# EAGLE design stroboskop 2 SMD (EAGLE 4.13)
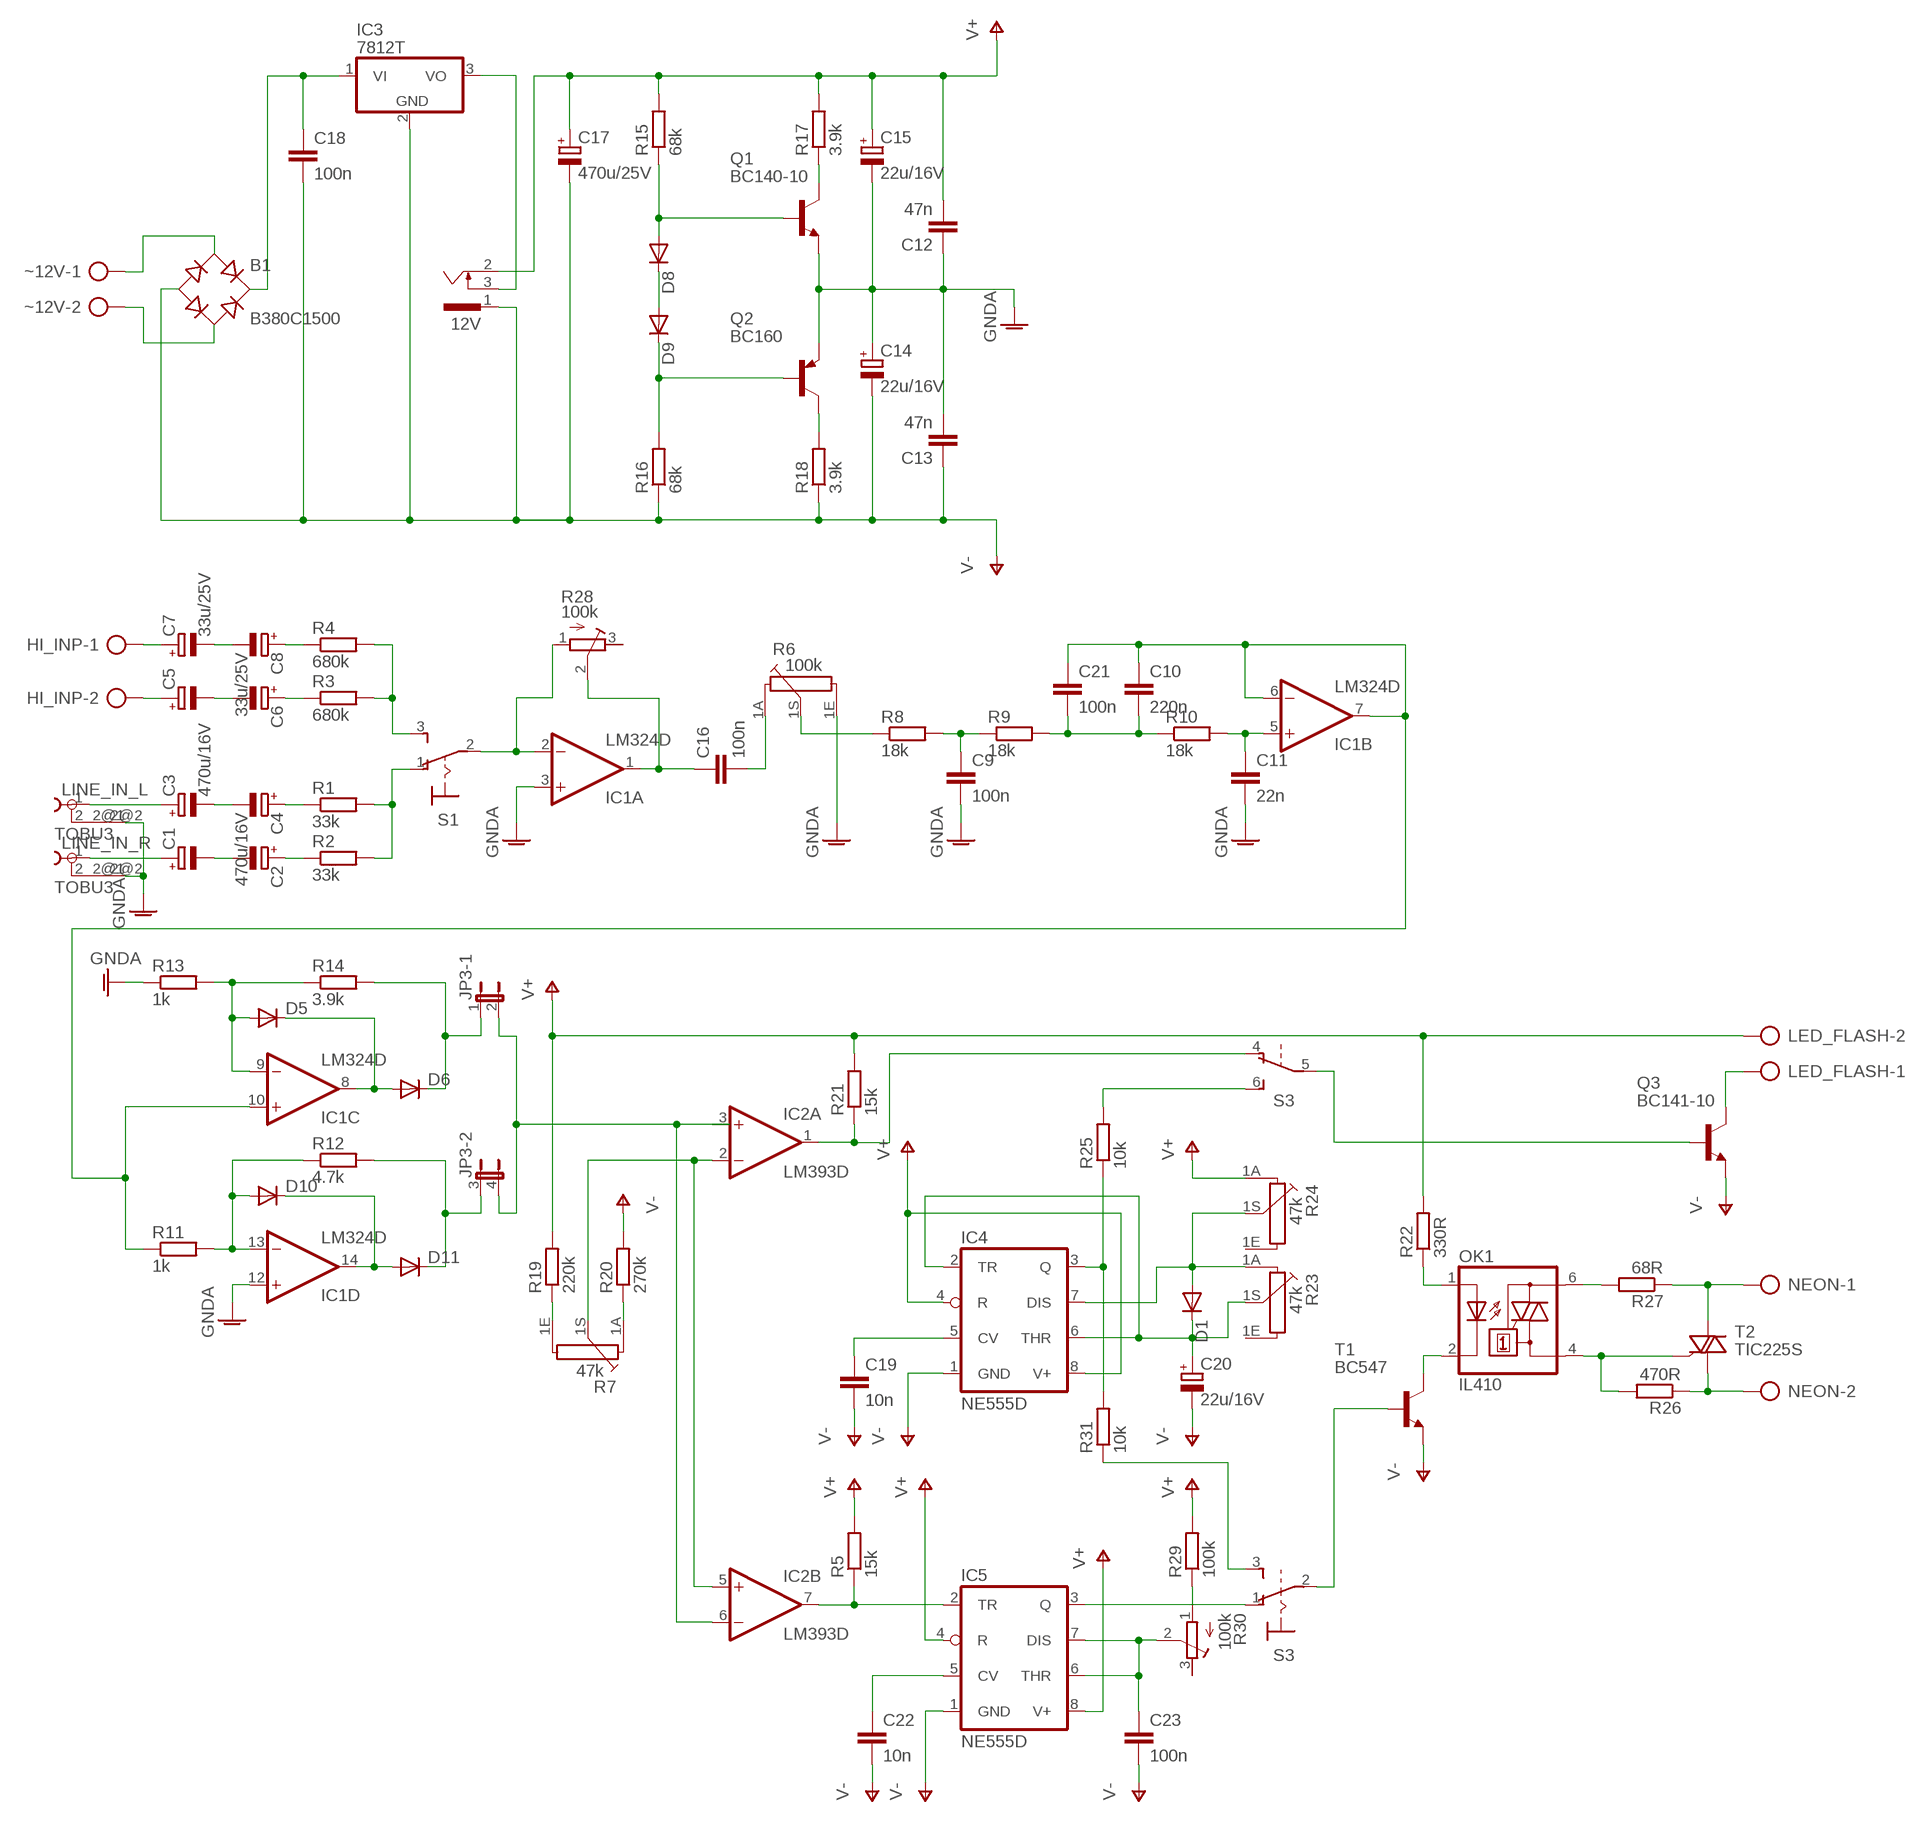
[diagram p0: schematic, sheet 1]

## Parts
12V  733989-55  [733989-5]
B1  B380C1500  RB1A  [RB1A]
C1  CPOL-EUE5-10.5  [E5-10,5]
C2  CPOL-EUE5-10.5  [E5-10,5]
C3  470u/16V  CPOL-EUE5-10.5  [E5-10,5]
C4  470u/16V  CPOL-EUE5-10.5  [E5-10,5]
C5  CPOL-EUE2.5-5  [E2,5-5]
C6  CPOL-EUE2.5-5  [E2,5-5]
C7  33u/25V  CPOL-EUE2.5-5  [E2,5-5]
C8  33u/25V  CPOL-EUE2.5-5  [E2,5-5]
C9  100n  C-EUC1206  [C1206]
C10  220n  C-EUC1206  [C1206]
C11  22n  C-EUC0805  [C0805]
C12  47n  C-EU050-025X075  [C050-025X075]
C13  47n  C-EU050-025X075  [C050-025X075]
C14  22u/16V  CPOL-EUE5-10.5  [E5-10,5]
C15  22u/16V  CPOL-EUE5-10.5  [E5-10,5]
C16  100n  C-EUC1206  [C1206]
C17  470u/25V  CPOL-EUE5-10.5  [E5-10,5]
C18  100n  C-EU050-025X075  [C050-025X075]
C19  10n  C-EUC0805  [C0805]
C20  22u/16V  CPOL-EUE2,5-6E  [E2,5-6E]
C21  100n  C-EUC1206  [C1206]
C22  10n  C-EUC0805  [C0805]
C23  100n  C-EUC1206  [C1206]
D1  DIODE-SOD80C  [SOD80C]
D5  DIODE-SOD80C  [SOD80C]
D6  DIODE-SOD80C  [SOD80C]
D8  DIODE-SOD80C  [SOD80C]
D9  DIODE-SOD80C  [SOD80C]
D10  DIODE-SOD80C  [SOD80C]
D11  DIODE-SOD80C  [SOD80C]
HI_INP  AK300/2  [AK300/2]
IC1  LM324D  [SO14]
IC2  LM393D  [SO08]
IC3  7812T  [TO220H]
IC4  NE555D  [SO08]
IC5  NE555D  [SO08]
JP3  JP2QE  [JP2Q]
LED_FLASH  AK300/2  [AK300/2]
LINE_IN_L  TOBU3  [TOBU3]
LINE_IN_R  TOBU3  [TOBU3]
NEON  AK300/2  [AK300/2]
OK1  IL410  [DIL06]
Q1  BC140-10  [TO39]
Q2  BC160  [TO39]
Q3  BC141-10  [TO39]
R1  33k  R-EU_M1206  [M1206]
R2  33k  R-EU_M1206  [M1206]
R3  680k  R-EU_M1206  [M1206]
R4  680k  R-EU_M1206  [M1206]
R5  15k  R-EU_M1206  [M1206]
R6  100k  PC16S  [PC16S]
R7  47k  PC16S  [PC16S]
R8  18k  R-EU_M1206  [M1206]
R9  18k  R-EU_M1206  [M1206]
R10  18k  R-EU_M1406  [M1406]
R11  1k  R-EU_M1206  [M1206]
R12  4.7k  R-EU_M1206  [M1206]
R13  1k  R-EU_M1206  [M1206]
R14  3.9k  R-EU_M1206  [M1206]
R15  68k  R-EU_M1206  [M1206]
R16  68k  R-EU_M1206  [M1206]
R17  3.9k  R-EU_M1206  [M1206]
R18  3.9k  R-EU_M1206  [M1206]
R19  220k  R-EU_M1206  [M1206]
R20  270k  R-EU_M1206  [M1206]
R21  15k  R-EU_M1206  [M1206]
R22  330R  R-EU_M1206  [M1206]
R23  47k  PC16S  [PC16S]
R24  47k  PC16S  [PC16S]
R25  10k  R-EU_M1206  [M1206]
R26  470R  R-EU_0309/12  [0309/12]
R27  68R  R-EU_0309/12  [0309/12]
R28  100k  R-TRIMM4G/J  [RTRIM4G/J]
R29  100k  R-EU_M1206  [M1206]
R30  100k  R-TRIMM4G/J  [RTRIM4G/J]
R31  10k  R-EU_M1206  [M1206]
S1  320-916  [320-916]
S3  320-938  [320-938]
T1  BC547  [TO92]
T2  TIC225S  [TO220DS]
~12V  AK300/2  [AK300/2]

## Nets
GNDA: C9.2 C11.2 C12.1 C13.2 C14.+ C15.- IC1.3(A:+IN) IC1.12(D:+IN) LINE_IN_L.2@2 LINE_IN_R.2@2 Q1.1(E) Q2.1(E) R6.1E R13.1
N$1: C7.- C8.-
N$2: C5.- C6.-
N$3: C3.- C4.-
N$4: C1.- C2.-
N$5: C4.+ R1.1
N$6: C2.+ R2.1
N$7: C8.+ R4.1
N$8: C6.+ R3.1
N$9: R3.2 R4.2 S1.3(S)
N$10: R1.2 R2.2 S1.1(O)
N$11: IC1.2(A:-IN) R28.1(E) S1.2(P)
N$12: C16.1 IC1.1(A:OUT) R28.2(S)
N$13: R6.1S R8.1
N$14: C9.1 R8.2 R9.1
N$15: C10.2 C21.2 R9.2 R10.1
N$16: C11.1 IC1.5(B:+IN) R10.2
N$17: C10.1 C21.1 IC1.6(B:-IN) IC1.7(B:OUT) IC1.10(C:+IN) R11.1
N$18: D10.A IC1.13(D:-IN) R11.2 R12.1
N$19: D10.C D11.A IC1.14(D:OUT)
N$20: D11.C JP3.3 R12.2
N$21: C16.2 R6.1A
N$22: D5.A IC1.9(C:-IN) R13.2 R14.1
N$23: D5.C D6.A IC1.8(C:OUT)
N$24: D6.C JP3.1 R14.2
N$25: IC2.3(A:+IN) IC2.6(B:-IN) JP3.2 JP3.4
N$26: IC2.2(A:-IN) IC2.5(B:+IN) R7.1S
N$27: C7.+ HI_INP.1
N$28: C5.+ HI_INP.2
N$29: C3.+ LINE_IN_L.1
N$30: C1.+ LINE_IN_R.1
N$31: IC2.1(A:OUT) R21.1 S3.4(B:O)
N$32: R7.1E R19.1
N$33: Q1.3(C) R17.1
N$34: Q2.3(C) R18.2
N$35: D8.A Q1.2(B) R15.1
N$36: D8.C D9.A
N$37: D9.C Q2.2(B) R16.2
N$38: R7.1A R20.1
N$39: LED_FLASH.1 Q3.3(C)
N$40: OK1.1(A) R22.1
N$41: OK1.2(C) T1.3(C)
N$42: B1.AC1 ~12V.1
N$43: B1.AC2 ~12V.2
N$44: B1.+ C18.1 IC3.1(VI)
N$45: R25.2 S3.6(B:S)
N$46: 12V.3 IC3.3(VO)
N$47: C19.1 IC4.5(CV)
N$48: C20.+ D1.C IC4.2(TR) IC4.6(THR) R23.1S
N$49: OK1.4(A1) R26.2 T2.G
N$50: D1.A IC4.7(DIS) R23.1A R24.1S
N$51: NEON.2 R26.1 T2.A1
N$52: IC4.3(Q) R25.1 R31.2
N$53: Q3.2(B) S3.5(B:P)
N$54: OK1.6(A2) R27.2
N$55: NEON.1 R27.1 T2.A2
N$60: IC2.7(B:OUT) IC5.2(TR) R5.1
N$69: C22.1 IC5.5(CV)
N$70: R29.1 R30.1(E)
N$71: C23.1 IC5.6(THR) IC5.7(DIS) R30.2(S)
N$72: S3.2(1:P) T1.2(B)
N$73: IC5.3(Q) S3.1(1:O)
N$74: R31.1 S3.3(1:S)
V+: 12V.2 C12.2 C15.+ C17.+ IC4.4(R) IC4.8(V+) IC5.4(R) IC5.8(V+) LED_FLASH.2 R5.2 R15.2 R17.2 R19.2 R21.2 R22.2 R24.1A R29.2
V-: 12V.1 B1.- C13.1 C14.- C17.- C18.2 C19.2 C20.- C22.2 C23.2 IC3.2(GND) IC4.1(GND) IC5.1(GND) Q3.1(E) R16.1 R18.1 R20.2 T1.1(E)
Unconnected: LINE_IN_L.2 LINE_IN_L.2@1 LINE_IN_R.2 LINE_IN_R.2@1 R23.1E R24.1E R28.3(A) R30.3(A)

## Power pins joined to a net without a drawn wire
V+: IC1.4(P:V+) IC2.8(P:V+)
V-: IC1.11(P:V-) IC2.4(P:V-)

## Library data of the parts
12V = con-conrad:733989-55: FEMALE PRINT CONNECTOR Außen-Ø 4,2 mm, Innen 1.1 mm FUK HING Industries, distributor Conrad
B1 = rectifier:RB1A: RECTIFIER 1 A
C1-C8 C14 C15 C17 C20 = rcl:CPOL-EU: POLARIZED CAPACITOR, European symbol
C9-C13 C16 C18 C19 C21-C23 = rcl:C-EU: CAPACITOR, European symbol
D1 D5 D6 D8-D11 = diode:DIODE-: DIODE
HI_INP LED_FLASH NEON ~12V = con-ptr500:AK300/2: CONNECTOR
IC1 = linear:LM324: OP AMP
IC2 = linear:LM393: COMPARATOR
IC3 = linear:78*: Positive VOLTAGE REGULATOR
IC4 IC5 = linear:*555: TIMER
JP3 = jumper:JP2QE: JUMPER
LINE_IN_L LINE_IN_R = con-hirschmann:TOBU3: Female Cinch CONNECTOR
OK1 = optocoupler:IL410: SIEMENS OPTO COUPLER
Q1 = transistor-npn:BC140-10: NPN Transistor
Q2 = transistor-pnp:BC160*: PNP Transistror
Q3 = transistor-npn:BC141-10: NPN Transistor
R1-R5 R8-R22 R25-R27 R29 R31 = rcl:R-EU_: RESISTOR, European symbol
R6 R7 R23 R24 = piher:PC16S: POTENTIOMETER single carbon potentiometer, 16 mm, S3ROH
R28 R30 = rcl:R-TRIMM: Trimm resistor
S1 = switch:320-916: TOGGLE SWITCH distributor RS Components
S3 = switch:320-938: TOGGLE SWITCH distributor RS Components
T1 = transistor:BC547: NPN TRANSISTOR
T2 = triac:TIC225S: TRIAC

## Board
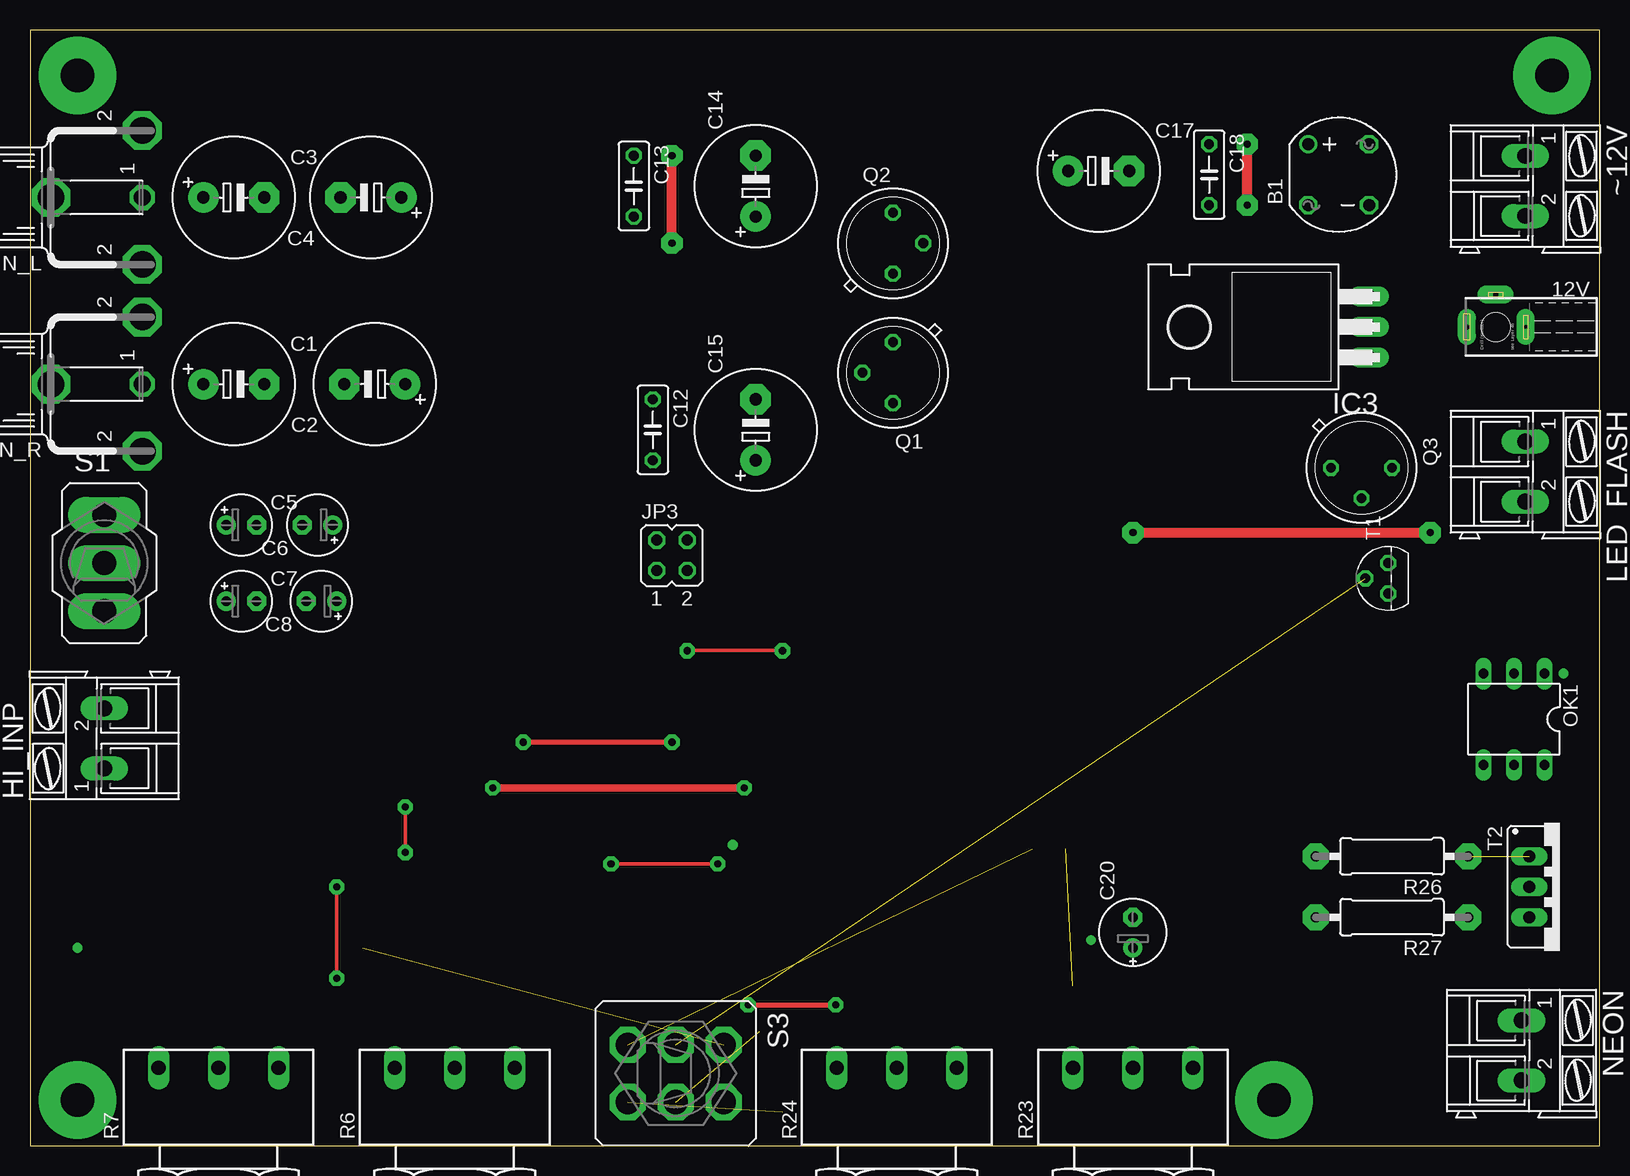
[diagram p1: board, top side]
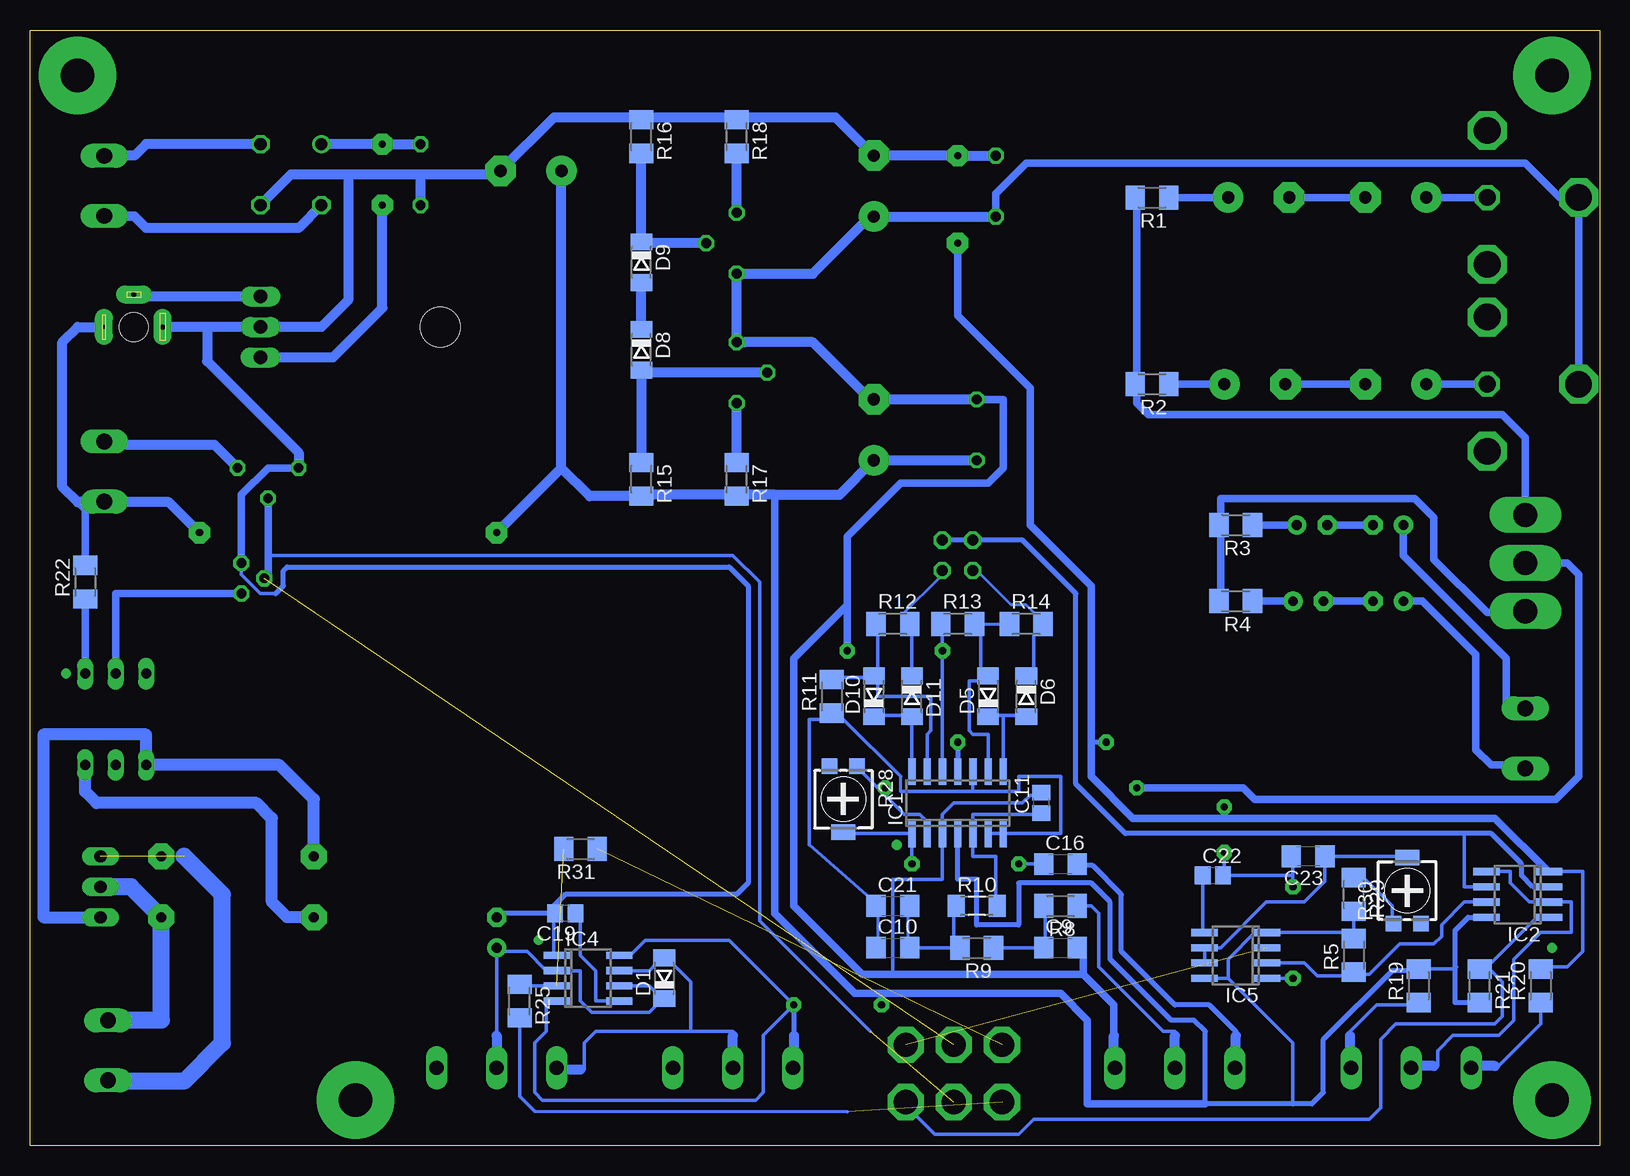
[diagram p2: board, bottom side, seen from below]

Size 130.8 x 93.02 mm. Coordinates in mm from the lower left corner, seen from the top.
Outline: 0,0 130.8,0 130.8,93.02 0,93.02 0,0
Copper layers (1*16): Top 0.035mm / dielectric 1.5mm / Bottom 0.035mm
Design rules "default": minimum track width 12mil, minimum drill 5mil, track to track 10mil, track to pad 10mil, pad to pad 10mil, via to via 10mil, smd to smd 10mil, copper to edge 40mil, drill to drill 8mil, minimum pad ring 10mil, minimum via ring 8mil, stop-mask expansion 4mil, vias tented up to drill 0mil, thermal gap 10mil

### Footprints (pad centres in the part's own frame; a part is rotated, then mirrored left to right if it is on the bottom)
733989-5 = drill 0.4 pad 1.5 long: 1 0,5.82; 3 2.7,3.42 | drill 0.3 pad 1.5 long: 2 0,0.92 | hole 2.4: 0,3.42
RB1A = drill 1.016 round: + -2.54,2.54 | drill 1.016 octagon: - 2.54,-2.54; AC1 2.54,2.54; AC2 -2.54,-2.54
E5-10,5 = drill 1.016 pad 2.54 round: + -2.54,0 | drill 1.016 pad 2.54 octagon: - 2.54,0
E2,5-5 = drill 0.813 pad 1.6 round: + -1.27,0 | drill 0.813 pad 1.6 octagon: - 1.27,0
C1206 = smd 1.6 x 1.8: 1 -1.4,0; 2 1.4,0
C0805 = smd 1.3 x 1.5: 1 -0.85,0; 2 0.85,0
C050-025X075 = drill 0.813 octagon: 1 -2.54,0; 2 2.54,0
E2,5-6E = drill 0.813 pad 1.575 round: + -1.27,0 | drill 0.813 pad 1.575 octagon: - 1.27,0
SOD80C = smd 1.4 x 1.8: A 1.7,0; C -1.7,0
AK300/2 = drill 1.321 long: 1 -2.515,0; 2 2.489,0
SO14 = smd 0.6 x 2.2: 1 -3.81,-2.6; 2 -2.54,-2.6; 3 -1.27,-2.6; 4 0,-2.6; 5 1.27,-2.6; 6 2.54,-2.6; 7 3.81,-2.6; 8 3.81,2.6; 9 2.54,2.6; 10 1.27,2.6; 11 0,2.6; 12 -1.27,2.6; 13 -2.54,2.6; 14 -3.81,2.6
SO08 = smd 0.6 x 2.2: 1 -1.905,-2.6; 2 -0.635,-2.6; 3 0.635,-2.6; 4 1.905,-2.6; 5 1.905,2.6; 6 0.635,2.6; 7 -0.635,2.6; 8 -1.905,2.6
TO220H = drill 1.118 long: 1 -2.54,-10.16; 2 0,-10.16; 3 2.54,-10.16 | hole 3.302: 0,4.826
JP2Q = drill 0.914 octagon: 1 -1.27,-1.27; 2 -1.27,1.27; 3 1.27,-1.27; 4 1.27,1.27
TOBU3 = drill 1.397 octagon: 1 0,-2.54 | drill 2.21 octagon: 2 5.588,-2.54; 2@1 -5.588,-2.54; 2@2 0,5.08
DIL06 = drill 0.813 long: 1 -2.54,-3.81; 2 0,-3.81; 3 2.54,-3.81; 4 2.54,3.81; 5 0,3.81; 6 -2.54,3.81
TO39 = drill 0.813 octagon: 1 0,-2.54; 2 2.54,0; 3 0,2.54
M1206 = smd 1.6 x 2: 1 -1.4,0; 2 1.4,0
PC16S = drill 1.2 long: 1A -5,6.5; 1E 5,6.5; 1S 0,6.5
M1406 = smd 1.4 x 1.8: 1 -1.7,0; 2 1.7,0
0309/12 = drill 0.813 octagon: 1 -6.35,0; 2 6.35,0
RTRIM4G/J = smd 1.3 x 1.3: 1 -1.15,-2.75; 3 1.15,-2.75 | smd 2 x 1.3: 2 0,2.75
320-916 = drill 2.007 long: 1 0,4.013; 2 0,0; 3 0,-4.013
320-938 = drill 2.007 octagon: 1 -2.388,4.013; 2 -2.388,0; 3 -2.388,-4.013; 4 2.388,4.013; 5 2.388,0; 6 2.388,-4.013
TO92 = drill 0.813 octagon: 1 1.27,0; 2 0,1.905; 3 -1.27,0
TO220DS = drill 1.016 long: A1 -2.54,-2.54; A2 0,-2.54; G 2.54,-2.54

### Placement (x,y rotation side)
12V  125.56,68.26 90 top
B1  109.06,80.96 0 top
C1  16.98,63.49 0 top
C2  28.73,63.49 180 top
C3  16.98,79.05 0 top
C4  28.41,79.05 180 top
C5  17.61,51.75 0 top
C6  23.96,51.75 180 top
C7  17.61,45.4 0 top
C8  24.28,45.4 180 top
C9  44.92,16.51 0 bottom
C10  58.89,16.51 0 bottom
C11  46.51,28.57 90 bottom
C12  51.91,59.68 270 top
C13  50.32,80.01 270 top
C14  60.48,80.01 90 top
C15  60.48,59.68 90 top
C16  44.92,23.49 0 bottom
C17  89.05,81.28 0 top
C18  98.26,80.96 270 top
C19  86.2,19.36 180 bottom
C20  91.91,17.78 90 top
C21  58.89,20 0 bottom
C22  32.22,22.54 0 bottom
C23  24.28,24.12 180 bottom
D1  77.94,13.96 90 bottom
D5  50.95,37.46 90 bottom
D6  47.78,37.46 270 bottom
D8  79.84,66.35 270 bottom
D9  79.84,73.66 270 bottom
D10  60.48,37.46 90 bottom
D11  57.3,37.46 270 bottom
HI_INP  6.18,33.97 90 top
IC1  53.49,28.57 0 bottom
IC2  6.82,20.95 90 bottom
IC3  101.44,68.26 90 top
IC4  84.29,13.96 270 bottom
IC5  30.32,15.87 90 bottom
JP3  53.49,49.21 0 top
LED_FLASH  124.61,56.19 270 top
LINE_IN_L  6.82,79.05 90 top
LINE_IN_R  6.82,63.49 90 top
NEON  124.3,7.93 270 top
OK1  123.66,35.55 180 top
Q1  71.91,64.45 180 top
Q2  71.91,75.24 0 top
Q3  110.96,56.51 270 top
R1  37.3,79.05 180 bottom
R2  37.3,63.49 180 bottom
R3  30.32,51.75 180 bottom
R4  30.32,45.4 180 bottom
R5  20.47,15.87 90 bottom
R6  35.4,-0.01 0 top
R7  15.71,-0.01 0 top
R8  44.92,20 180 bottom
R9  51.91,16.51 180 bottom
R10  51.91,20 0 bottom
R11  63.97,37.46 90 bottom
R12  58.89,43.49 0 bottom
R13  53.49,43.49 0 bottom
R14  47.78,43.49 0 bottom
R15  79.84,55.56 270 bottom
R16  79.84,84.13 270 bottom
R17  71.91,55.56 270 bottom
R18  71.91,84.13 270 bottom
R19  15.07,13.33 90 bottom
R20  4.92,13.33 90 bottom
R21  9.99,13.33 270 bottom
R22  126.2,46.98 90 bottom
R23  91.91,-0.01 0 top
R24  72.23,-0.01 0 top
R25  90.01,12.06 270 bottom
R26  113.5,24.12 180 top
R27  113.5,19.05 180 top
R28  63.02,28.89 180 bottom
R29  20.47,20.95 270 bottom
R30  16.03,21.27 0 bottom
R31  84.92,24.76 180 bottom
S1  6.18,48.57 0 top
S3  53.81,6.03 270 top
T1  113.18,47.3 90 top
T2  127.47,21.59 270 top
~12V  124.61,80.01 270 top

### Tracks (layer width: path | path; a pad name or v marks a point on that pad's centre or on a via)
GNDA  (via drill 0.6 pad 1.27)
  Top 0.305: v62.7,41.27 v54.76,41.27
  Bottom 0.254: 71.27,66.99 Q1.1 72.23,66.67 | 54.76,42.54 R13.1 | 43.01,15.87 C9.2
  Bottom 0.305: 54.76,42.54 v54.76,41.27 IC1.12 | 58.89,14.28 58.89,22.22 54.76,22.22 IC1.3 54.76,27.62 53.81,28.57 48.1,28.57 47.46,29.21 46.82,29.21 46.51,29.52 C11.2
  Bottom 0.61: LINE_IN_R.2@2 LINE_IN_L.2@2 3.33,79.05 6.18,81.91 47.78,81.91 50.32,79.37 C13.2 | C12.1 49.68,62.22 49.68,56.51 50.95,55.24 58.25,55.24 62.7,50.79 62.7,45.08 | 43.01,14.28 43.01,15.87 | 43.01,14.28 58.89,14.28 61.43,14.28 67.15,20 67.15,40.63 62.7,45.08 | 62.7,45.08 v62.7,41.27 | 40.47,9.2 40.47,11.74 43.01,14.28
  Bottom 0.813: C13.2 C14.+ 61.43,76.83 65.56,72.7 Q2.1 Q1.1 | C12.1 C15.- 61.43,62.86 65.56,66.99 71.27,66.99 | R6.1E 40.39,6.42 40.47,6.34 40.47,9.2
N$1
  Bottom 0.61: C7.- C8.-
N$2
  Bottom 0.61: C5.- C6.-
N$3
  Bottom 0.61: C3.- C4.-
N$4
  Bottom 0.61: C1.- C2.-
N$5
  Bottom 0.61: C4.+ R1.1
N$6
  Bottom 0.61: C2.+ R2.1
N$7
  Bottom 0.61: C8.+ R4.1
N$8
  Bottom 0.61: C6.+ R3.1
N$9
  Bottom 0.254: 31.59,46.35 R4.2 | R3.2 31.59,50.79
  Bottom 0.61: 31.59,50.79 31.59,46.35 | R3.2 31.71,51.93 31.59,52.06 31.59,53.97 15.39,53.97 13.8,52.38 13.8,48.89 9.36,44.45 6.18,44.45 S1.3
N$10
  Bottom 0.254: 38.57,78.1 R1.2 | 38.57,64.45 R2.2
  Bottom 0.61: 38.57,78.1 38.57,64.45 38.57,61.91 37.62,60.95 8.09,60.95 6.18,59.05 S1.1
N$11  (via drill 0.6 pad 1.27)
  Top 0.61: v38.57,29.84 v59.53,29.84
  Bottom 0.254: 61.43,31.11 R28.1 | 56.03,26.98 IC1.2
  Bottom 0.305: 60.16,29.84 57.94,27.62 56.67,27.62 56.03,26.98 | 60.16,29.84 61.43,31.11 | v59.53,29.84 60.16,29.84
  Bottom 0.61: S1.2 2.69,48.57 1.74,47.62 1.74,30.79 3.65,28.89 28.73,28.89 29.68,29.84 v38.57,29.84 38.89,29.84
N$12  (via drill 0.6 pad 1.27)
  Top 0.305: v48.41,23.49 v57.3,23.49
  Bottom 0.254: 62.07,26.03 R28.2 | IC1.1 57.3,26.03
  Bottom 0.305: 57.3,26.03 62.07,26.03 | v57.3,23.49 IC1.1 | 46.19,23.49 C16.1 v48.41,23.49
N$13
  Bottom 0.305: R8.1 42.38,20 41.75,19.36 41.75,14.92 36.35,9.52 35.39,9.52 35.39,9.2
  Bottom 0.813: R6.1S 35.39,9.2
N$14
  Bottom 0.254: C9.1 46.19,17.14 | 46.19,19.05 R8.2
  Bottom 0.305: 46.19,17.14 46.19,19.05 | C9.1 R9.1
N$15
  Bottom 0.254: C10.2 57.62,17.14 57.62,19.36 C21.2 | 53.81,19.36 R10.1 | R9.2 53.81,17.46
  Bottom 0.305: R9.2 C10.2 | 53.81,17.46 53.81,19.36
N$16
  Bottom 0.254: 47.14,27.62 C11.1 | IC1.5 52.22,26.98
  Bottom 0.305: 47.14,27.62 52.22,27.62 52.22,26.98 | IC1.5 52.22,24.12 50.32,24.12 50.32,20 R10.2
N$17
  Bottom 0.254: 50.95,26.03 IC1.6 | C10.1 60.16,17.14 60.16,19.36 C21.1 60.79,20.63 65.87,25.08 | 58.25,29.52 58.25,30.79 | 63.02,35.55 R11.1 64.92,35.55 | 52.22,30.16 IC1.10 | 49.68,26.03 IC1.7
  Bottom 0.305: 50.95,26.03 49.68,26.03 44.92,26.03 44.92,30.79 48.41,30.79 48.41,29.52 52.22,29.52 | 58.25,30.79 63.02,35.55 | 52.22,29.52 58.25,29.52 | 52.22,29.52 52.22,30.16 | 65.87,25.08 65.87,35.55 64.92,35.55
N$18
  Bottom 0.254: D10.A 61.11,39.05 | 63.02,39.05 R11.2 | 60.16,42.54 R12.1 | D10.A 60.16,39.68 | 60.16,38.73 D10.A
  Bottom 0.305: 61.11,39.05 63.02,39.05 | 60.16,39.68 60.16,42.54 | 60.16,38.73 60.16,37.46 55.71,37.46 55.71,34.6 56.03,34.28 IC1.13
N$19
  Bottom 0.305: D10.C 59.84,35.87 57.94,35.87 D11.A IC1.14
N$20
  Bottom 0.254: 57.3,42.54 R12.2 57.94,44.45 55.08,47.3 JP3.3
  Bottom 0.305: D11.C 57.3,42.54
N$21
  Bottom 0.305: C16.2 43.65,23.49 43.52,23.36
  Bottom 0.406: 43.52,23.36 42.25,23.36 39.84,20.95 39.84,16.19 35.39,11.74 32.54,11.74 30.32,9.52 30.32,9.2
  Bottom 0.813: R6.1A 30.39,6.58 30.32,6.66 30.32,9.2
N$22
  Bottom 0.254: 51.59,39.68 D5.A 51.59,38.73 | R13.2 R14.1
  Bottom 0.305: 51.59,39.68 51.59,42.54 R13.2 | 51.59,38.73 52.54,38.73 52.54,34.6 52.22,34.28 50.95,34.28 IC1.9
N$23
  Bottom 0.254: 48.41,35.87 D6.A | 50.32,35.87 D5.C
  Bottom 0.305: 49.68,35.87 50.32,35.87 | 49.68,35.87 48.41,35.87 | IC1.8 49.68,35.87
N$24
  Bottom 0.254: D6.C 47.14,39.68 | JP3.1 51.59,47.62 49.05,45.08 47.78,45.08 47.14,44.45 R14.2
  Bottom 0.305: 47.14,39.68 47.14,42.54 R14.2
N$25
  Bottom 0.305: IC2.6 11.27,21.59 11.27,26.03
  Bottom 0.406: IC2.3 5.55,21.59 6.5,22.54 6.5,23.49 9.04,26.03 11.27,26.03 39.52,26.03 43.65,30.16 43.65,46.03 48.1,50.48 JP3.2 JP3.4
N$26
  Bottom 0.305: 13.8,6.66 13.49,6.66 13.49,7.93 12.22,9.2 8.41,9.2 7.14,10.47 7.14,15.55 4.92,17.78 2.38,17.78 2.38,20.32 IC2.2 5.87,20.32 7.46,21.9 7.46,22.86 IC2.5
  Bottom 0.813: R7.1S 15.71,6.66 13.8,6.66
N$27
  Bottom 0.61: HI_INP.1 7.78,31.7 | 7.78,31.7 8.09,31.75 | C7.+ 14.76,45.4 10.31,40.95 10.31,33.02 9.04,31.75 7.77,31.75 7.78,31.74 7.78,31.7
N$28
  Bottom 0.61: C5.+ 16.34,49.21 7.77,40.63 7.77,36.51 HI_INP.2
N$29
  Bottom 0.61: LINE_IN_L.1 C3.+
N$30
  Bottom 0.61: LINE_IN_R.1 C1.+
N$31
  Bottom 0.254: 9.04,15.23 R21.1 9.04,14.6 | 5.23,19.05 IC2.1
  Bottom 0.305: 9.04,15.23 5.23,19.05 | 9.04,14.6 8.09,13.65 8.09,10.79 8.72,10.15 16.98,10.15 18.25,8.88 18.25,3.17 19.2,2.22 47.14,2.22 48.41,0.95 55.4,0.95 57.94,3.49 57.82,3.6 S3.4
N$32
  Bottom 0.305: 20.79,9.2 20.79,9.52 18.57,11.74 15.39,11.74 15.07,12.06 R19.1
  Bottom 0.813: R7.1E 20.71,6.42 20.79,6.34 20.79,9.2
N$33
  Bottom 0.813: R17.1 Q1.3
N$34
  Bottom 0.813: Q2.3 R18.2
N$35
  Bottom 0.254: 79.21,64.45 D8.A
  Bottom 0.813: D8.A R15.1 | Q1.2 79.21,64.45
N$36
  Bottom 0.813: D8.C D9.A
N$37
  Bottom 0.254: 79.21,75.24 D9.C
  Bottom 0.813: Q2.2 79.21,75.24 | D9.C R16.2
N$38
  Bottom 0.305: 4.92,12.06 R20.1 4.92,10.15 8.41,6.66 8.72,6.66
  Bottom 0.61: R7.1A 10.71,6.58 10.63,6.66
  Bottom 0.813: 8.72,6.66 10.63,6.66
N$39
  Bottom 0.813: LED_FLASH.1 122.71,58.41 115.4,58.41 Q3.3
N$40
  Bottom 0.61: 126.2,45.71 R22.1 OK1.1
N$41
  Bottom 0.61: OK1.2 123.66,46.03 T1.3
N$42
  Bottom 0.813: B1.AC1 121.12,83.5 122.07,82.55 ~12V.1
N$43
  Bottom 0.813: B1.AC2 108.42,76.51 121.12,76.51 122.07,77.47 ~12V.2
N$44  (via drill 0.6 pad 1.78)
  Top 0.813: v101.43,78.42 v101.43,83.5
  Bottom 0.813: IC3.1 105.56,65.72 101.43,69.84 v101.43,78.42 | C18.1 v101.43,83.5 B1.+
N$45  (1 unrouted)
  Bottom 0.305: 62.7,2.83 88.73,2.85 90.01,4.12 R25.2
N$46
  Bottom 0.813: 12V.3 122.23,70.96 122.39,70.8 IC3.3
N$47
  Bottom 0.305: C19.1 84.92,18.73 84.92,15.87 83.65,14.6 83.65,12.06 IC4.5
N$48
  Bottom 0.305: IC4.6 79.21,13.33 78.57,12.69 D1.C 78.57,11.74 79.21,11.11 83.97,11.11 84.92,12.06 84.92,14.6 IC4.2 87.78,14.6 89.37,16.19 91.28,16.19 C20.+ 91.91,9.2
  Bottom 0.813: 91.91,9.2 R23.1S
N$49
  Bottom 1.016: R26.2 107.15,28.89 110.01,31.75 OK1.4 121.12,34.28 129.69,34.28 129.69,19.05 T2.G
N$50
  Bottom 0.305: IC4.7 79.21,14.6 78.57,15.23 D1.A 77.31,15.23 75.72,13.65 75.72,9.52 | 72.23,9.2 72.23,9.52 75.72,9.52 | 75.72,9.52 83.65,9.52 84.61,8.57 84.61,6.34 84.92,6.34
  Bottom 0.813: R24.1S 72.23,9.2 | 84.92,6.34 87.15,6.34 R23.1A
N$51  (2 unrouted)
  Bottom 1.422: 117.95,24.12 114.77,20.95 114.77,8.57 117.95,5.39 124.29,5.39 NEON.2
N$52  (1 unrouted)
  Bottom 0.305: R25.1 89.05,13.33 IC4.3
N$53  (1 unrouted)
  Bottom 0.305: 110.96,49.21 72.23,49.21 70,46.98 70,18.73 60.79,9.52
  Bottom 0.61: 110.96,47.62 110.96,49.21 Q3.2
N$54
  Bottom 1.016: OK1.6 126.2,29.52 125.25,28.57 111.91,28.57 110.64,27.3 110.64,20.32 109.37,19.05 R27.2
N$55
  Bottom 1.422: T2.A2 122.39,21.59 R27.1 119.85,10.47 124.29,10.47 NEON.1
N$56  (via drill 0.6 pad 2.18)
  other vias: 107.15,24.12
N$57  (via drill 0.6 pad 2.18)
  other vias: 107.15,19.05
N$58  (via drill 0.6 pad 2.18)
  other vias: 119.85,24.12
N$59  (via drill 0.6 pad 2.18)
  other vias: 119.85,19.05
N$60
  Bottom 0.305: IC2.7 11.27,20.32 13.17,18.41 13.17,17.46 13.8,16.82 16.66,16.82 19.2,14.28 20.47,14.28 | IC5.2 24.6,15.23 23.52,14.15 20.6,14.15 20.47,14.28 | 20.47,14.28 20.29,14.47 R5.1 20.47,14.28
N$61  (via drill 0 pad 0.81)
  other vias: 58.57,25.08
N$62  (via drill 0 pad 0.81)
  other vias: 88.42,17.14
N$63  (via drill 0 pad 0.81)
  other vias: 127.79,39.36
N$64  (via drill 0 pad 0.81)
  other vias: 3.96,16.51
N$65  (via drill 2.8 pad 6.45)
  other vias: 3.96,3.81
N$66  (via drill 2.8 pad 6.45)
  other vias: 103.66,3.81
N$67  (via drill 2.8 pad 6.45)
  other vias: 3.96,89.21
N$68  (via drill 2.8 pad 6.45)
  other vias: 126.84,89.21
N$69
  Bottom 0.305: IC5.5 32.86,17.78 33.07,17.99 C22.1
N$70
  Bottom 0.305: R29.1 19.65,22.35 17.3,20 17.3,19.05 16.98,18.73 17.18,18.53 R30.1
N$71
  Bottom 0.305: IC5.7 32.86,15.23 32.92,15.29 IC5.6 31.59,16.51 27.77,20.32 24.6,20.32 22.88,22.03 C23.1 | R30.2 16.03,24.12 C23.1 | C23.1 23.01,24.12
N$72  (1 unrouted)
N$73  (1 unrouted)
N$74  (1 unrouted)
V+  (via drill 0.6 pad 1.27, 0.6 pad 1.78)
  Top 0.406: v59.84,11.74 v67.15,11.74
  Top 0.813: v91.91,51.11 v116.67,51.11
  Bottom 0.254: R17.2 72.86,54.29 | 78.89,54.29 R15.2
  Bottom 0.305: IC4.4 87.78,12.06 87.78,9.52 88.73,8.57 88.73,4.44 88.1,3.81 70.32,3.81 69.68,4.44 69.68,9.2 v67.15,11.74 72.54,17.14 79.53,17.14 80.8,15.87 IC4.8 | 30.95,13.96 IC5.8 | 30.95,13.96 25.55,8.57 25.55,3.49 | 30.95,13.96 30.95,15.55 28.73,17.78 IC5.4 20.47,17.78 20.47,17.46 | 20.47,17.46 R5.2 | 20.47,17.46 R29.2 | 12.03,14.92 11.9,14.92 12.09,14.73 R19.2
  Bottom 0.406: R21.2 12.03,11.93 12.03,14.92 12.03,17.96 10.95,19.05 IC2.8 | IC1.4 53.49,22.22 51.9,22.22 51.9,18.41 48.41,18.41 48.41,21.9 42.38,21.9 40.79,20.32 40.79,15.55 35.71,10.47 33.81,10.47 32.86,9.52 32.86,3.49 25.55,3.49 23.96,3.49 23.01,4.44 23.01,8.88 17.3,14.6 15.39,14.6 15.26,14.73 R19.2 | v67.15,11.74 67.15,9.2 | 59.84,12.69 v59.84,11.74
  Bottom 0.61: 32.86,3.49 42.7,3.49 42.7,10.47 44.92,12.69 59.84,12.69 62.07,12.69 68.73,19.36 68.73,54.29 | R22.2 126.2,53.02 126.84,53.65
  Bottom 0.813: 72.86,54.29 78.89,54.29 | C12.2 C15.+ 63.33,54.29 68.73,54.29 71.91,54.29 R17.2 | 12V.2 126.84,68.26 128.11,66.99 128.11,54.92 126.84,53.65 124.61,53.65 | 124.61,53.65 LED_FLASH.2 | R15.2 84.16,54.16 86.51,56.51 | 86.51,56.51 C17.+ | 124.61,53.65 119.21,53.65 v116.67,51.11 | 86.51,56.51 v91.91,51.11 | R24.1A 67.23,6.58 67.15,6.66 67.15,9.2
V-  (via drill 0.6 pad 1.27, 0.6 pad 1.78)
  Top 0.305: v25.55,21.59 v25.55,13.96 | v31.27,28.25 v31.27,24.44
  Top 0.406: v41.11,33.65 v53.49,33.65
  Top 0.813: v53.49,75.24 v53.49,82.55
  Bottom 0.254: 4.6,14.92 R20.2 4.79,14.73 | R18.1 72.86,85.72 | 78.89,85.72 R16.1
  Bottom 0.305: IC2.4 4.28,22.86 1.42,22.86 1.42,16.19 2.69,14.92 4.6,14.92 4.79,14.73 | 110.32,46.03 111.59,46.03 113.18,47.62 T1.1 | IC4.1 87.15,15.87 87.15,18.73 C19.2 87.15,19.36 | v25.55,13.96 IC5.1 | 25.55,22.54 v25.55,21.59 | 31.27,22.54 25.55,22.54 | C23.2 25.68,23.94 25.55,23.81 25.55,22.54 | 31.27,22.54 C22.2 | v31.27,24.44 31.27,22.54 | 31.27,27.3 v31.27,28.25
  Bottom 0.406: v53.49,33.65 IC1.11 | 42.38,33.65 v41.11,33.65 | C20.- 91.28,19.36 87.15,19.36 87.15,20 86.2,20.95 71.91,20.95 70.95,21.9 70.95,46.67 72.54,48.25 109.37,48.25 109.69,47.94 109.69,46.67 110.32,46.03
  Bottom 0.61: Q3.1 110.96,56.51 113.18,54.29 T1.1 | v53.49,75.24 53.49,69.21 47.46,63.18 47.46,51.75 42.38,46.67 42.38,33.65 42.38,30.79 38.89,27.3 31.27,27.3 8.72,27.3 4.28,22.86
  Bottom 0.813: 72.86,85.72 78.89,85.72 | R18.1 72.23,85.72 63.65,85.72 C14.- v53.49,82.55 C13.1 | B1.- 109.06,80.96 104.29,80.96 | 98.26,80.96 91.91,80.96 C17.- 87.15,85.72 79.84,85.72 R16.1 | 98.26,80.96 104.29,80.96 | 98.26,80.96 C18.2 | 116.04,68.26 111.91,68.26 111.59,68.58 IC3.2 106.51,68.26 104.29,70.48 104.29,80.96 | 116.04,68.26 12V.1 | 116.04,68.26 116.04,65.4 108.42,57.78 Q3.1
